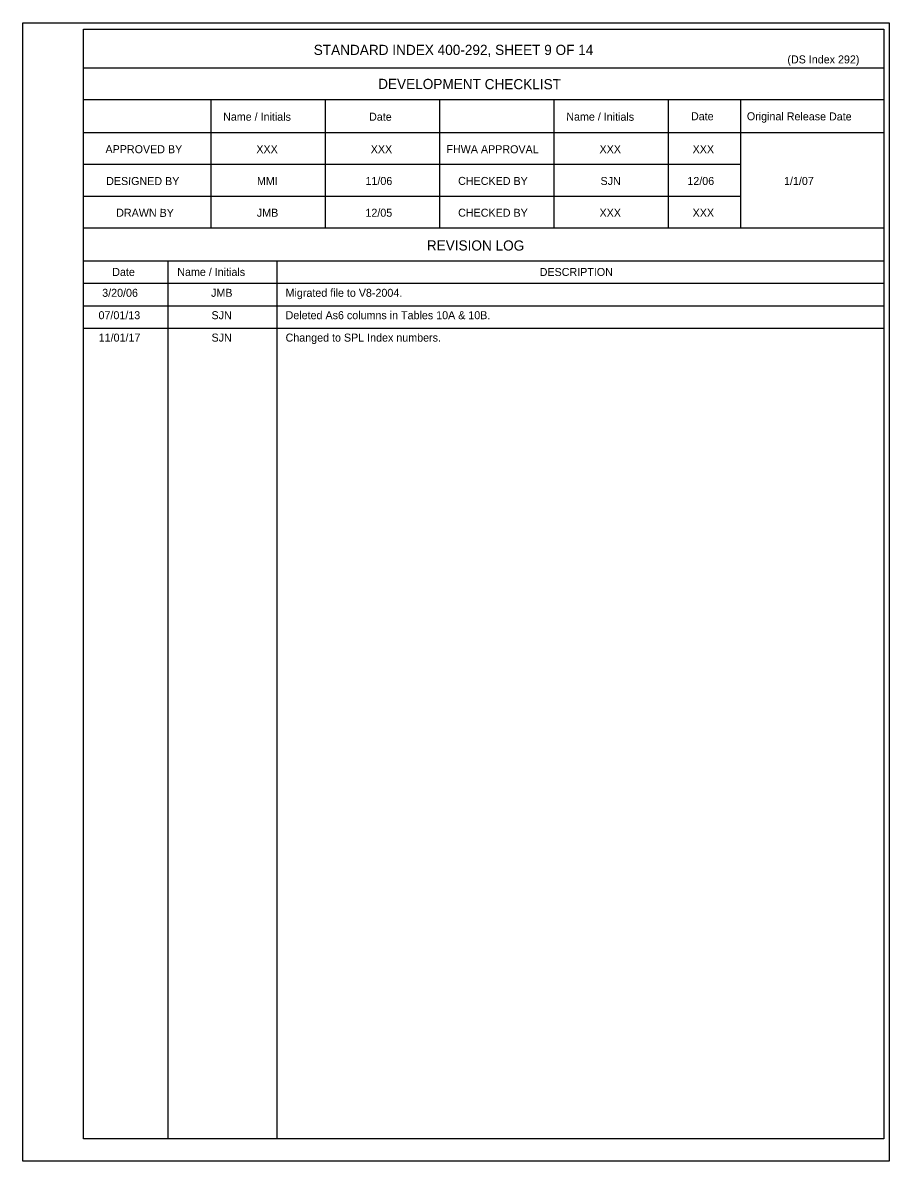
# Model space of a CAD drawing. Extents: x 10338.56 to 10340.78, y 76371.55 to 76372.62.
# Drawn here: x 10340.094 to 10340.775, y 76371.667 to 76372.563 of the extents above; entities that cross this region are included whole.
import ezdxf

# ---------------------------------------------------------------- set-up
doc = ezdxf.new("R2010")
doc.units = 0
doc.layers.add('AdhocPoint_dp', color=7, linetype='Continuous')
doc.layers.add('Border', color=7, linetype='Continuous')

msp = doc.modelspace()

# ---------------------------------------------------------------- linework, layer by layer
at = {"layer": 'AdhocPoint_dp'}
for p, q in [((10340.14142, 76372.34008), (10340.77101, 76372.34008)), ((10340.14142, 76372.32247), (10340.77101, 76372.32247))]:
    msp.add_line(p, q, dxfattribs=at)
at = {"layer": 'Border'}
for p, q in [((10340.77101, 76372.52706), (10340.14142, 76372.52706)), ((10340.77101, 76372.50206), (10340.14142, 76372.50206)), ((10340.24142, 76372.50206), (10340.24142, 76372.40119)), ((10340.33142, 76372.50206), (10340.33142, 76372.40119)), ((10340.42142, 76372.50206), (10340.42142, 76372.40119)), ((10340.51142, 76372.50206), (10340.51142, 76372.40119)), ((10340.60142, 76372.50206), (10340.60142, 76372.40119)), ((10340.65814, 76372.50206), (10340.65814, 76372.40119)), ((10340.77101, 76372.47619), (10340.14142, 76372.47619)), ((10340.65814, 76372.45119), (10340.14142, 76372.45119)), ((10340.65814, 76372.42619), (10340.14142, 76372.42619)), ((10340.77101, 76372.40119), (10340.14142, 76372.40119)), ((10340.77101, 76372.37532), (10340.14142, 76372.37532)), ((10340.20768, 76372.37532), (10340.20768, 76371.68449)), ((10340.29338, 76372.37532), (10340.29338, 76371.68449)), ((10340.77101, 76372.3577), (10340.14142, 76372.3577)), ((10340.0936, 76371.66695), (10340.0936, 76371.66695))]:
    msp.add_line(p, q, dxfattribs=at)
for points in [[(10340.0936, 76372.56278), (10340.77526, 76372.56278), (10340.77526, 76371.66695), (10340.0936, 76371.66695)], [(10340.14143, 76372.5577), (10340.77101, 76372.5577), (10340.77101, 76371.68449), (10340.14143, 76371.68449)]]:
    msp.add_lwpolyline(points, close=True, dxfattribs=at)

# ---------------------------------------------------------------- texts
at = {"layer": 'AdhocPoint_dp'}
for s, height, p in [('STANDARD INDEX 400-292, SHEET 9 OF 14', 0.008, (10340.3225, 76372.53745)), ('(DS Index 292)', 0.0063, (10340.69515, 76372.5308)), ('XXX', 0.0063, (10340.27736, 76372.46015)), ('XXX', 0.0063, (10340.36736, 76372.46015)), ('XXX', 0.0063, (10340.54736, 76372.46015)), ('XXX', 0.0063, (10340.62059, 76372.46015)), ('MMI', 0.0063, (10340.27785, 76372.43515)), ('11/06', 0.0063, (10340.36322, 76372.43515)), ('SJN', 0.0063, (10340.54812, 76372.43515)), ('12/06', 0.0063, (10340.61645, 76372.43515)), ('1/1/07', 0.0063, (10340.69251, 76372.43515)), ('JMB', 0.0063, (10340.27777, 76372.41015)), ('12/05', 0.0063, (10340.36318, 76372.41015)), ('XXX', 0.0063, (10340.54736, 76372.41015)), ('XXX', 0.0063, (10340.62059, 76372.41015)), ('DESCRIPTION', 0.0063, (10340.50028, 76372.36354)), ('3/20/06', 0.0063, (10340.15609, 76372.34714)), ('JMB', 0.0063, (10340.24173, 76372.34714)), ('Migrated file to V8-2004.', 0.0063, (10340.30036, 76372.34714)), ('07/01/13', 0.0063, (10340.15319, 76372.32952)), ('SJN', 0.0063, (10340.24209, 76372.32952)), ('Deleted As6 columns in Tables 10A & 10B.', 0.0063, (10340.30036, 76372.32952)), ('11/01/17', 0.0063, (10340.15333, 76372.3119)), ('SJN', 0.0063, (10340.24209, 76372.3119)), ('Changed to SPL Index numbers.', 0.0063, (10340.30036, 76372.3119))]:
    msp.add_text(s, height=height, dxfattribs=at).set_placement(p)
for s, height, p in [('DEVELOPMENT CHECKLIST', 0.008, (10340.37317, 76372.51071)), ('Name / Initials', 0.0063, (10340.25119, 76372.48578)), ('Date', 0.0063, (10340.36602, 76372.48573)), ('Name / Initials', 0.0063, (10340.52119, 76372.48578)), ('Date', 0.0063, (10340.6193, 76372.48609)), ('Original Release Date', 0.0063, (10340.66326, 76372.48608)), ('APPROVED BY', 0.0063, (10340.15866, 76372.46021)), ('FHWA APPROVAL', 0.0063, (10340.42689, 76372.46021)), ('DESIGNED BY', 0.0063, (10340.15919, 76372.43515)), ('CHECKED BY', 0.0063, (10340.43611, 76372.43521)), ('DRAWN BY', 0.0063, (10340.16709, 76372.41015)), ('CHECKED BY', 0.0063, (10340.43611, 76372.41021)), ('REVISION LOG', 0.008, (10340.41145, 76372.38365)), ('Date', 0.0063, (10340.16399, 76372.36356)), ('Name / Initials', 0.0063, (10340.21514, 76372.36361))]:
    msp.add_text(s, height=height, rotation=359.87563, dxfattribs=at).set_placement(p)

doc.saveas('drawing.dxf')
